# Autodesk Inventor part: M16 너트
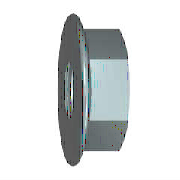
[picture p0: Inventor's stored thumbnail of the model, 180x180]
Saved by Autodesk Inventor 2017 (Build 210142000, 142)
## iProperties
IsCustomPart: 0
Created: 2009-02
Part Number: M16 너트
Material: 강철, 연강
Document SubType Name: Modeling
Standard: JIS B 1190
Designer: mdu
Standards Organization: JIS
Language: ko-KR
Size Designation: M 16
Categories: <MemberInstance><Categories><Category DisplayName="조임쇠" InternalName="e4da775c-781d-43d5-af7c-5136215cf5a6" Mnemonic="FSTN"><Category DisplayName="너트" InternalN
Density: 1 g/cm^3
Appearance: 니켈
Author: mdu
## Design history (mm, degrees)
sketch "스케치1"
  geometry: L1 (-3.414, 0)-(18.069, 0) reference; L2 (6.015, 11)-(3.359, 15.6); L3 (6.015, 11)-(15, 11); L4 (15, 11)-(15, 0); L5 (6.015, 11)-(6.015, 0); L6 (0, -3.378)-(0, 20.266) reference; A1 r 1.8 centre (1.8, 14.7) between (3.359, 15.6) and (0, 14.7); 1 further point
  constraints: 8 end point, 3 point on line, 2 perpendicular, 2 point on circle, 2 tangent, 1 centre point, 1 parallel
  dimensions: "d2" = 22 diameter of L3 L1 (= SW); "d4" = 33 dimension on A1 L1 (= LADI); "d5" = 1.8 radius of A1 (= PHH); "d15" = 15 distance between parallel lines of L4 L6 (= KOH); "d16" = 30 deg angle of L6 L2 (= KEWI)
revolve "링" sketch "스케치1" stored, may be unused: angle "d8" = 90 deg
sketch "스케치2"
  geometry: L1 (-11, -6.351)-(-11, 6.351); L2 (-11, 6.351)-(0, 12.702); L3 (0, 12.702)-(11, 6.351); L4 (11, 6.351)-(11, -6.351); L5 (11, -6.351)-(0, -12.702); L6 (0, -12.702)-(-11, -6.351); C1 r 4.9 at (0, 0); C2 r 14.7 at (0, 0) reference; 1 further point
  constraints: 12 end point, 1 centre point, 1 coincident, 1 vertical, 11 other
  dimensions: "d6" = 25.40341 distance of L5.end L2.end (= 1.1547 x SW)
extrude "본체" join sketch "스케치2" distance "d7" = 15 (= KOH); taper "d9" = 0 deg
sketch "스케치3"
  geometry: L1 (5.032, 12.702)-(15, 12.702) reference; L2 (15, 6.351)-(15, 12.702) reference; L3 (0, -14.7)-(0, 14.7) reference; L4 (-3, 0)-(18, 0) reference; L5 (14.018, 12.702)-(15, 11)
  constraints: 2 end point, 2 point on line
  dimensions: "d10" = 30 deg angle of L2 L5 (= ANG1); "d11" = 22 diameter of L5.end L4 (= SW0)
revolve "모따기1" sketch "스케치3" stored, may be unused: angle "d24" = 90 deg
sketch "스케치4"
  geometry: C1 r 14.7 at (0, 0) reference; 1 further point
  constraints: 1 coincident
hole "스레드" sketch "스케치4" at (0, 0) diameter "d25" = 13.835; stored, may be unused: countersink angle "d29" = 82 deg, drill point angle "d31" = 118 deg; dims "d26" = 6, "d27" = 4, "d28" = 2, "d30" = 8
workaxis "Work Axis1"
workplane "Work Plane1"
body "Solid1"
chamfer "모따기2" distance "d12" = 1.08253 (= -0.5 x GD1 + 0.5 x NND); stored, may be unused: angle "d13" = 30 deg, second distance "d46" = 1.08253 (= -0.5 x GD1 + 0.5 x NND)
chamfer "모따기3" distance "d51" = 1.08253 (= -0.5 x GD1 + 0.5 x NND); stored, may be unused: second distance "d52" = 2, angle "d53" = 45 deg
other parameters: "ANG1" = 30 deg [user parameter; used in 1 equation term], "KEWI" = 30 deg [user parameter; used in 1 equation term], "NND" = 16 [user parameter; used in 3 equation terms], "LADI" = 33 [user parameter; used in 2 equation terms], "SW" = 22 [user parameter; used in 4 equation terms], "PHH" = 1.8 [user parameter; used in 2 equation terms], "KOH" = 15 [user parameter; used in 2 equation terms], "SW0" = 22 (= SW) [user parameter; used in 1 equation term], "GD1" = 13.83494 (computed from THREADDIA, PTC, TOA) [user parameter; used in 3 equation terms], "d1" = 33 (= LADI), "d3" = 1.8 (= PHH), "d45" = 0, "d47" = 0, "d49" = 0, "d54" = 0, "GUL" = 1.08253 (= 0.541266 x PTC) [user parameter], "TPU" = 5 (computed from PTC) [user parameter], "RR" = 2 [user parameter], "THREADDIA" = 16 [user parameter; used in 1 equation term], "TOA" = 30 deg [user parameter; used in 1 equation term], "PTC" = 2 [user parameter; used in 4 equation terms], "GAL" = 1.08253 (= 0.541266 x PTC) [user parameter], "E0" = 25.41 (= 1.155 x SW) [user parameter]
